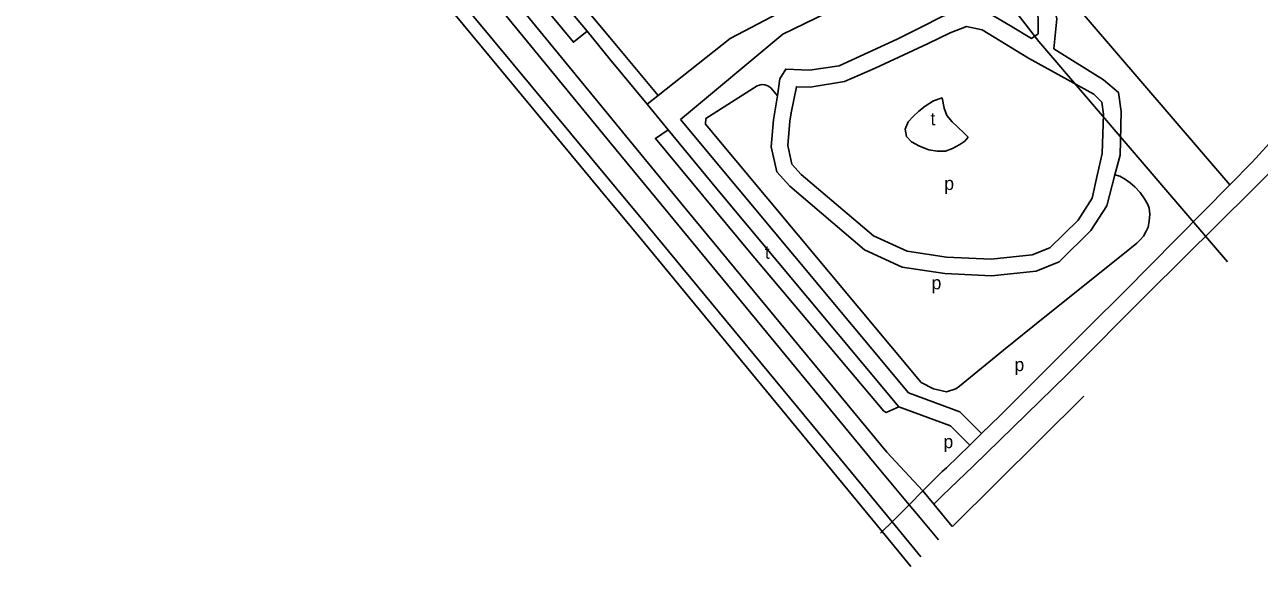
# Model space of a CAD drawing. Extents: x 156721 to 158827, y 386657 to 388950.
# Drawn here: x 157871.8 to 158247.8, y 386656.5 to 386821.6 of the extents above; entities that cross this region are included whole.
import ezdxf

# ---------------------------------------------------------------- set-up
doc = ezdxf.new("R2010")
doc.units = 0
for name, color, linetype in [('BLT_Basislijn', 7, 'Continuous'), ('BLT_Centroide', 7, 'Continuous'), ('BLT_Hoogspanningsmast_en_leidingen', 7, 'Continuous'), ('BLT_Spoorlijn', 7, 'Continuous'), ('BLT_Vlakafsluiter', 7, 'Continuous')]:
    doc.layers.add(name, color=color, linetype=linetype)

msp = doc.modelspace()

# ---------------------------------------------------------------- linework, layer by layer
at = {"layer": 'BLT_Basislijn'}
for p, q in [((158043.03, 386819.55), (158050, 386811.09)), ((158050, 386811.09), (158061.36, 386797.31)), ((158064.67, 386799.98), (158061.36, 386797.31)), ((158061.36, 386797.31), (158067.78, 386789.53)), ((158146.01, 386796.78), (158148.58, 386798.39)), ((158148.58, 386798.39), (158151.2, 386799.3)), ((158151.2, 386799.3), (158151.78, 386796.16)), ((158140.87, 386791.96), (158142.39, 386793.63)), ((158142.39, 386793.63), (158144.06, 386795.25)), ((158144.06, 386795.25), (158146.01, 386796.78)), ((158151.78, 386796.16), (158152.63, 386793.92)), ((158152.63, 386793.92), (158154.2, 386791.92)), ((158067.78, 386789.53), (158082.56, 386771.59)), ((158071.51, 386792.65), (158140.97, 386709.37)), ((158079.15, 386791.3), (158144.81, 386712.57)), ((158139.87, 386789.77), (158140.87, 386791.96)), ((158140.34, 386787.53), (158139.87, 386789.77)), ((158154.2, 386791.92), (158155.87, 386790.49)), ((158155.87, 386790.49), (158157.92, 386788.53)), ((158267.21, 386792.63), (158213.95, 386739.79)), ((158141.87, 386785.92), (158140.34, 386787.53)), ((158144.3, 386784.53), (158141.87, 386785.92)), ((158158.11, 386786.11), (158156.54, 386785.06)), ((158157.92, 386788.53), (158159.11, 386787.34)), ((158159.11, 386787.34), (158158.11, 386786.11)), ((158147.11, 386783.44), (158144.3, 386784.53)), ((158149.63, 386783.06), (158147.11, 386783.44)), ((158152.16, 386783.01), (158149.63, 386783.06)), ((158154.3, 386783.87), (158152.16, 386783.01)), ((158156.54, 386785.06), (158154.3, 386783.87)), ((158082.56, 386771.59), (158137.98, 386705.14)), ((158206.51, 386740.09), (158238.77, 386772.79)), ((158194.37, 386708.36), (158154.31, 386668.67)), ((158159.59, 386693.46), (158163.19, 386696.94)), ((158152.46, 386686.56), (158159.59, 386693.46)), ((158145.34, 386679.49), (158151.22, 386685.37)), ((158151.22, 386677.99), (158160.63, 386687.04)), ((158151.22, 386685.37), (158152.46, 386686.56)), ((158145.34, 386679.49), (158148.66, 386675.44)), ((158148.66, 386675.44), (158151.22, 386677.99)), ((158148.66, 386675.44), (158154.26, 386668.63))]:
    msp.add_line(p, q, dxfattribs=at)
for points in [[(157648.04, 387289.7), (157544.83, 387414.91), (157472.21, 387499.44), (157437.72, 387541.12), (157436.87, 387543.75), (157439.78, 387545.45), (157442.04, 387545.5), (157456.85, 387528.49), (157499.46, 387477.15), (157606.86, 387347.11), (157687.66, 387250), (157720.52, 387210.5), (157729.65, 387199.36), (157875.7, 387021.05), (157907.43, 386982.75), (157930.36, 386955.08), (157970.6, 386906.98), (158033.86, 386830.67), (158043.03, 386819.55)], [(158064.67, 386799.98), (158050, 386817.63), (158031.12, 386840.35), (157972.29, 386911.55), (157913.47, 386982.75), (157908.84, 386988.36), (157891.22, 387009.92), (157816.86, 387100), (157729.65, 387207.88), (157695.61, 387250), (157574.66, 387396.74), (157506.93, 387478.89), (157495.28, 387493.01), (157484.63, 387513.61), (157485.73, 387516.66)], [(157648.04, 387289.7), (157718.27, 387204.49), (157897.14, 386987.42), (158038.9, 386816.21), (158043.03, 386819.55)], [(157928.85, 386939.83), (158007.82, 386845.12), (158053.87, 386788.96)], [(158335.97, 386879.97), (158320.52, 386863.71), (158306.53, 386848.65), (158279.89, 386819.58), (158259.93, 386796.26), (158253.01, 386787.79), (158245.61, 386779.7), (158238.77, 386772.79)], [(158166.31, 386849.88), (158173.65, 386844.1), (158184.2, 386831.5), (158186.09, 386823.36), (158185.2, 386814.26)], [(158168.89, 386851.2), (158177.16, 386844.67), (158238.77, 386772.79)], [(158161.36, 386847.35), (158159.37, 386846.33), (158102.69, 386818.7), (158071.51, 386792.65)], [(158100.99, 386799.86), (158101.71, 386805.08), (158103.57, 386808.05), (158110.8, 386807.67), (158119.86, 386809.05), (158128.68, 386813.08), (158137.5, 386817.11), (158144.43, 386820.62), (158151.37, 386824.12), (158158.38, 386826.64), (158165.64, 386825.03), (158172.04, 386821.22), (158178.43, 386817.41), (158180.42, 386818.83), (158180.44, 386823.7), (158179.53, 386828.49), (158171.5, 386838.52), (158165.77, 386843.23), (158161.36, 386847.35)], [(158064.67, 386799.98), (158086.62, 386817.35), (158101.37, 386825.05)], [(158105.15, 386794.72), (158106.82, 386802.66), (158110.95, 386802.53), (158121.47, 386804.21), (158130.74, 386808.31), (158146.69, 386815.71), (158153.62, 386819.1), (158158.58, 386821), (158163.4, 386820.02), (158177.47, 386811.35), (158197.4, 386800.38), (158199.85, 386797.91), (158200.34, 386794.28), (158199.92, 386782.35), (158198.36, 386775.62)], [(158185.2, 386814.26), (158200.34, 386804.72), (158204.89, 386800.95), (158205.7, 386795.11), (158205.36, 386781.82), (158203.81, 386775.77)], [(158079.15, 386791.3), (158079.26, 386792.94), (158094.82, 386802.94), (158095.53, 386803.18), (158096.28, 386803.32), (158097.17, 386803.25), (158098.12, 386802.91), (158098.74, 386802.5), (158099.01, 386802.32), (158100.99, 386799.86)], [(158100.99, 386799.86), (158099.84, 386792.55), (158099.16, 386784.39), (158100.79, 386776.75), (158104.76, 386772.33), (158127.54, 386752.99), (158139.04, 386747.68), (158152, 386745.74), (158166.21, 386745.08), (158179.82, 386746.49), (158186.79, 386749.34), (158196.47, 386758.83), (158201.3, 386766.37), (158203.81, 386775.77)], [(158105.15, 386794.72), (158104.82, 386792.13), (158104.21, 386784.72), (158105.4, 386779.1), (158108.26, 386775.93), (158130.25, 386757.24), (158140.49, 386752.52), (158152.49, 386750.72), (158166.07, 386750.09), (158178.59, 386751.39), (158183.99, 386753.6), (158192.57, 386762), (158196.84, 386768.67), (158198.36, 386775.62)], [(158067.78, 386789.53), (158063.88, 386786.91), (158092.49, 386752.38), (158133.43, 386703.79), (158134.13, 386703.37), (158137.98, 386705.14)], [(158053.87, 386788.96), (158071.54, 386767.4), (158134.34, 386691.25), (158145.34, 386679.49)], [(158203.81, 386775.77), (158205.25, 386775.4), (158207.03, 386774.44), (158208.46, 386773.35), (158209.91, 386772.12), (158211.48, 386770.42), (158212.84, 386768.51), (158213.79, 386766.73), (158214.2, 386765.64), (158214.48, 386763.87), (158214.2, 386761.68), (158213.93, 386759.91), (158213.18, 386758.41), (158212.5, 386757.11), (158211.61, 386756.09), (158210.52, 386754.99), (158206.7, 386751.93), (158181.94, 386732.1), (158169.87, 386722.41), (158156.45, 386711.44), (158155.4, 386710.6), (158152.54, 386709.67), (158148.51, 386710.56), (158144.81, 386712.57)], [(158160.63, 386687.04), (158189.06, 386714.74), (158213.95, 386739.79)], [(158163.19, 386696.94), (158168.87, 386702.44), (158196.19, 386729.77), (158206.51, 386740.09)], [(158163.19, 386696.94), (158156.52, 386703.61), (158140.97, 386709.37)], [(158159.59, 386693.46), (158153.76, 386699.3), (158137.98, 386705.14)]]:
    msp.add_lwpolyline(points, dxfattribs=at)
at = {"layer": 'BLT_Hoogspanningsmast_en_leidingen'}
for q in [(158173.28, 386825.92), (158238.08, 386749.29)]:
    msp.add_line((158180.59, 386816.49), q, dxfattribs=at)
at = {"layer": 'BLT_Spoorlijn'}
for points in [[(158003.95, 386841.95), (158050, 386785.79)], [(158002.54, 386831.29), (158050, 386774.11)], [(158002.39, 386825.18), (158050, 386767.73)], [(158050, 386785.79), (158067.69, 386764.22)], [(158050, 386774.11), (158061.58, 386760.15)], [(158050, 386767.73), (158057.2, 386759.05)], [(158067.69, 386764.22), (158130.48, 386688.07)], [(158061.58, 386760.15), (158122.18, 386686.82)], [(158057.2, 386759.05), (158116.23, 386687.29)], [(158130.48, 386688.07), (158141.14, 386675.28)], [(158116.23, 386687.29), (158132.93, 386667.07)], [(158122.18, 386686.82), (158135.94, 386670.08)], [(158141.14, 386675.28), (158144.48, 386671.28)], [(158135.94, 386670.08), (158144.69, 386659.42)], [(158144.48, 386671.28), (158150.05, 386664.58)], [(158132.93, 386667.07), (158141.66, 386656.5)]]:
    msp.add_lwpolyline(points, dxfattribs=at)
at = {"layer": 'BLT_Vlakafsluiter'}
for p, q in [((158145.34, 386679.49), (158141.14, 386675.28)), ((158141.14, 386675.28), (158135.94, 386670.08)), ((158135.94, 386670.08), (158132.93, 386667.07)), ((158132.93, 386667.07), (158132.44, 386666.58))]:
    msp.add_line(p, q, dxfattribs=at)

# ---------------------------------------------------------------- texts
at = {"layer": 'BLT_Centroide'}
for s, p in [('t', (158147.65, 386790.92)), ('p', (158151.83, 386771.2)), ('t', (158097.2, 386750.24)), ('p', (158147.96, 386740.92)), ('p', (158173.22, 386715.99)), ('p', (158151.59, 386692.52))]:
    msp.add_text(s, height=4, dxfattribs=at).set_placement(p)

doc.saveas('drawing.dxf')
